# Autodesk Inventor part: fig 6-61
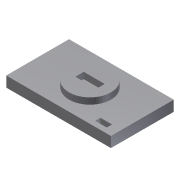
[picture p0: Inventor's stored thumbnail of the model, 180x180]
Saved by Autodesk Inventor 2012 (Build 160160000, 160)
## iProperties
Created: 2007-01
Part Number: fig 6-61
Document SubType Name: Modeling
Designer: Administrator
Density: 1 g/cm^3
Material: Default
Author: Administrator
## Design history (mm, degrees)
sketch "Sketch1"
  geometry: L1 (-50, 30)-(50, 30); L2 (50, 30)-(50, -30); L3 (50, -30)-(-50, -30); L4 (-50, -30)-(-50, 30); 1 further point
  constraints: 8 end point, 2 parallel, 1 horizontal, 1 perpendicular, 1 other
  dimensions: "d0" = 50 distance from line of L4 point (0, 0); "d1" = 100 distance of L1.start L1.end; "d2" = 30 distance from line of L3 point (0, 0); "d3" = 60 distance between parallel lines of L3 L1
extrude "Extrusion1" new body sketch "Sketch1" distance "d4" = 10; taper "d5" = 0 deg
sketch "Sketch2"
  geometry: L1 (10, -4)-(-10, -4); L2 (-10, -4)-(-10, 4); L3 (-10, 4)-(10, 4); L4 (10, 4)-(10, -4); C1 r 20 at (0, 0); 1 further point
  constraints: 8 end point, 2 parallel, 1 centre point, 1 coincident, 1 horizontal, 1 perpendicular, 1 other
  dimensions: "d6" = 40 diameter of C1; "d7" = 4 distance from line of L3 point (0, 0); "d8" = 8 distance between parallel lines of L1 L3; "d9" = 10 distance from line of L2 point (0, 0); "d10" = 20 distance between parallel lines of L4 L2
extrude "Extrusion2" join sketch "Sketch2" distance "d11" = 6; taper "d12" = 0 deg
sketch "Sketch3"
  geometry: L1 (30, -20)-(41, -20); L2 (41, -20)-(41, -25); L3 (41, -25)-(30, -25); L4 (30, -25)-(30, -20)
  constraints: 8 end point, 2 parallel, 1 horizontal, 1 perpendicular
extrude "Extrusion3" cut sketch "Sketch3" stored distance "d13" = 10; taper "d14" = 0 deg
body "Solid1"
